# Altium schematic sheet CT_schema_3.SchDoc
size 461 x 327 mm
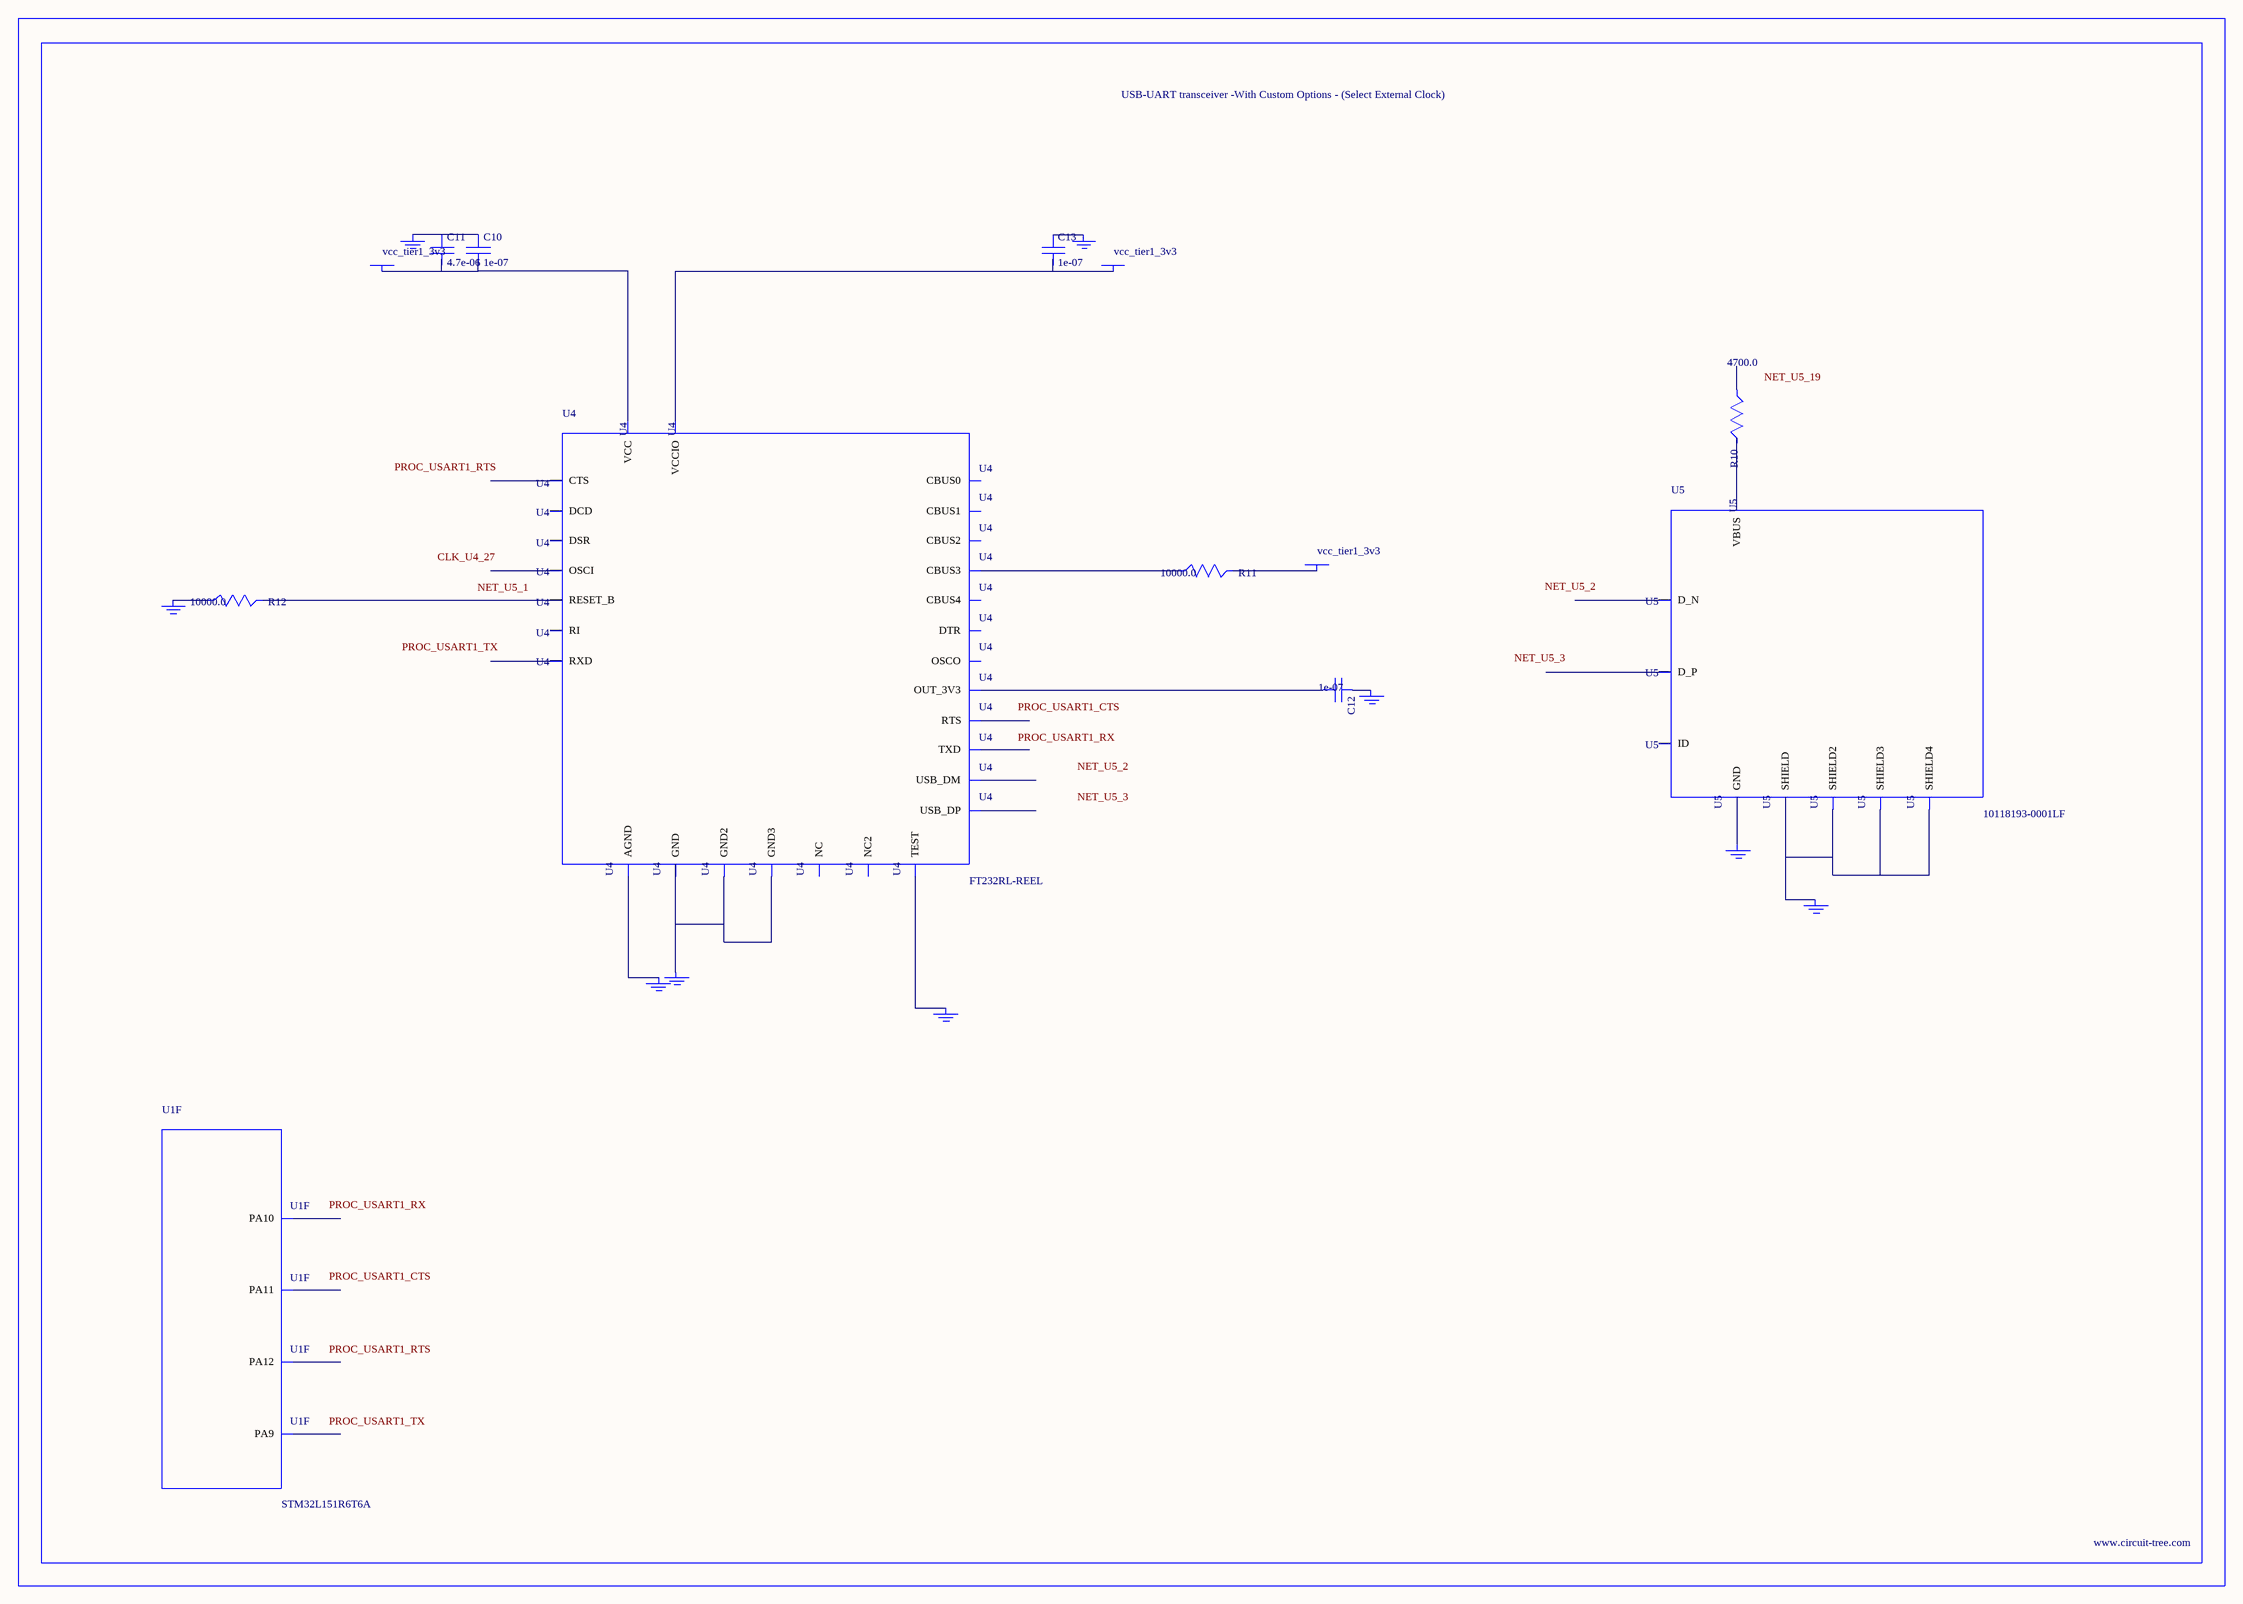
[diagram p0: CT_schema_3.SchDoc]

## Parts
BORDER2  (no value)
C10  1e-07  [C0402]
C11  4.7e-06  [C0805]
C12  1e-07  [C0402]
C13  1e-07  [C0402]
GND_INSTANCE_2_0  (no value)
GND_INSTANCE_2_1  (no value)
GND_INSTANCE_2_2  (no value)
GND_INSTANCE_2_3  (no value)
GND_INSTANCE_2_4  (no value)
GND_INSTANCE_2_5  (no value)
GND_INSTANCE_2_6  (no value)
GND_INSTANCE_2_7  (no value)
GND_INSTANCE_2_8  (no value)
POWER_INSTANCE_2_0  vcc_tier1_3v3
POWER_INSTANCE_2_1  vcc_tier1_3v3
POWER_INSTANCE_2_2  vcc_tier1_3v3
R10  4700.0  [R0603]
R11  10000.0  [R0603]
R12  10000.0  [R0603]
U1  STM32L151R6T6A  [LQFP64]  (part F of 7)
U4  FT232RL-REEL  [SSOP-28]
U5  10118193-0001LF  [FCI_10118193-0001LF]

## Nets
NetC10_1: C10.1 C11.1 GND_INSTANCE_2_3.0(GND)
NetC10_2: C10.2 C11.2 POWER_INSTANCE_2_2.0(PWR) U4.20(VCC)
NetC12_1: C12.1 GND_INSTANCE_2_1.0(GND)
NetC12_2: C12.2 U4.17(OUT_3V3)
NetC13_1: C13.1 GND_INSTANCE_2_0.0(GND)
NetC13_2: C13.2 POWER_INSTANCE_2_0.0(PWR) U4.4(VCCIO)
NetGND_INSTANCE_2_2_0: GND_INSTANCE_2_2.0(GND) R12.1
NetGND_INSTANCE_2_4_0: GND_INSTANCE_2_4.0(GND) U4.25(AGND)
NetGND_INSTANCE_2_5_0: GND_INSTANCE_2_5.0(GND) U4.26(TEST)
NetGND_INSTANCE_2_6_0: GND_INSTANCE_2_6.0(GND) U4.7(GND) U4.18(GND2) U4.21(GND3)
NetGND_INSTANCE_2_7_0: GND_INSTANCE_2_7.0(GND) U5.6(SHIELD) U5.7(SHIELD2) U5.8(SHIELD3) U5.9(SHIELD4)
NetGND_INSTANCE_2_8_0: GND_INSTANCE_2_8.0(GND) U5.5(GND)
NetPOWER_INSTANCE_2_1_0: POWER_INSTANCE_2_1.0(PWR) R11.2
NetR10_2: R10.2 U5.1(VBUS)
NetR11_1: R11.1 U4.14(CBUS3)
NetR12_2: R12.2 U4.19(RESET_B)

Not connected (* = marked no-connect by the designer): R10 1; U1 42(PA9) 43(PA10) 44(PA11) 45(PA12); U4 1(TXD) 2(DTR) 3(RTS) 5(RXD) 6(RI) 8(NC) 9(DSR) 10(DCD) 11(CTS) 12(CBUS4) 13(CBUS2) 15(USB_DP) 16(USB_DM) 22(CBUS1) 23(CBUS0) 24(NC2) 27(OSCI) 28(OSCO); U5 2(D_N) 3(D_P) 4(ID)

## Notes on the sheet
- Labels drawn without touching a wire or pin: CLK_U4_27, NET_U5_1, NET_U5_2, NET_U5_3, NET_U5_19, PROC_USART1_CTS, PROC_USART1_RTS, PROC_USART1_RX, PROC_USART1_TX

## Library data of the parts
BORDER2 = BORDER_PAGE2
C10 C12 C13 = C0402C104K3RACTU
C11 = C0805C475K4RACTU
GND_INSTANCE_2_0-GND_INSTANCE_2_8 = GND
POWER_INSTANCE_2_0-POWER_INSTANCE_2_2 = PWR
R10 = RC0603JR-074K7L
R11 R12 = RC0603JR-0710KL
